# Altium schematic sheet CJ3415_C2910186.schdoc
size 127 x 101 mm
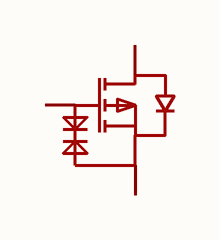
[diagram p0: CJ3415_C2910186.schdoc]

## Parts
Q?  cj3415  [SOT-23-3_L2.9-W1.3-P1.90-LS2.4-BR]  (value not drawn)

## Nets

Not connected (* = marked no-connect by the designer): Q? 1(G) 2(S) 3(D)

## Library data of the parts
Q? = cj3415: 数量:1个P沟道;漏源电压(Vdss):20V;连续漏极电流(Id):4A;导通电阻(RDS(on)):100mΩ@1.8V;耗散功率(Pd):1.3W;阈值电压(Vgs(th)):1V;; Manufacturer: CJ(江苏长电/长晶); Symbol: CJ3415_C2910186; AddInBom: yes; ModelId: c62791f0466c4ae2a892c056b845b0ca; ModelName: SOT-23-3P_L2.9-W1.3-H1.0-LS2.4-P0.95; ModelTransform: 98.425,114.173,0,180,0,0,0.0005,-0.0005,0; Number: 1个P沟道; Drain to Source Voltage: 20V; Current - Continuous Drain(Id): 4A; Pd - Power Dissipation: 1.3W; Gate Threshold Voltage (Vgs(th)): 1V; Gate Charge(Qg): 17.2nC@4.5V; Input Capacitance(Ciss): 1.45nF; Reverse Transfer Capacitance (Crss@Vds): 160pF; Type: P沟道; Output Capacitance(Coss): 205pF; Vgs: ±8V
